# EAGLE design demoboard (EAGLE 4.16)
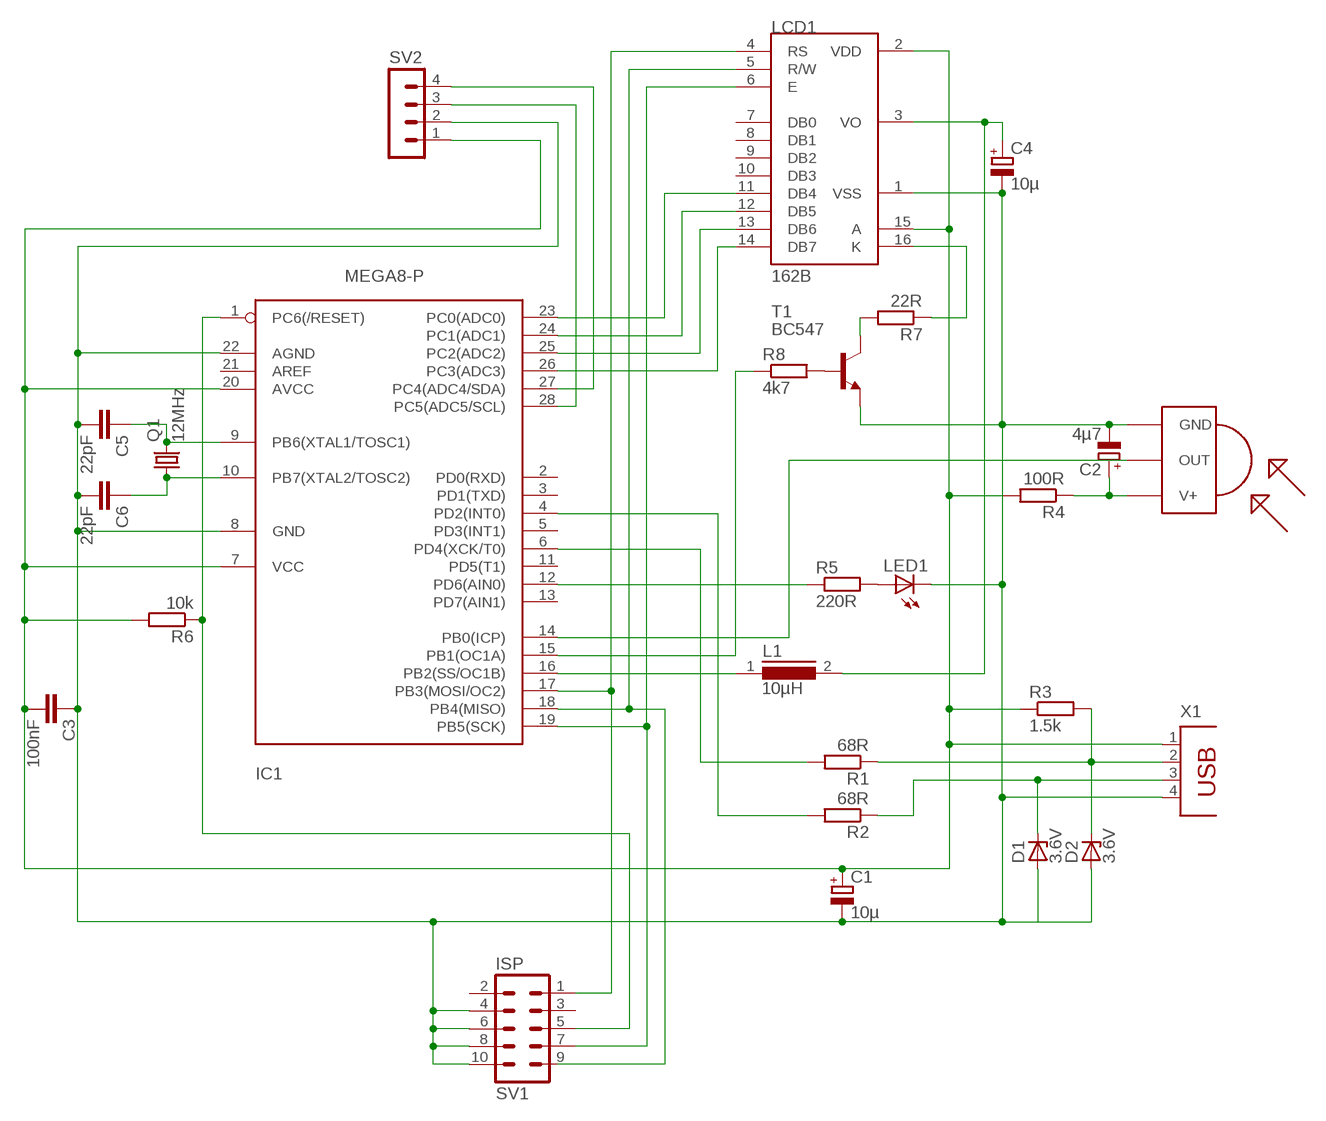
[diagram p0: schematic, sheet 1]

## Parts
C1  10µ  CPOL-EUE2.5-6  [E2,5-6]
C2  4µ7  CPOL-EUE2.5-6  [E2,5-6]
C3  100nF  C-EU025-025X050  [C025-025X050]
C4  10µ  CPOL-EUE2.5-6  [E2,5-6]
C5  22pF  C-EU025-025X050  [C025-025X050]
C6  22pF  C-EU025-025X050  [C025-025X050]
D1  3.6V  1N4728  [DO41Z10]
D2  3.6V  1N4728  [DO41Z10]
IC1  MEGA8-P  [DIL28-3]
L1  10µH  MICC10  [MICC10]
LCD1  162B  [162B]
LED1  LED3MM  [LED3MM]
Q1  12MHz  CRYSTALHC49S  [HC49/S]
R1  68R  R-EU_0309/10  [0309/10]
R2  68R  R-EU_0309/10  [0309/10]
R3  1.5k  R-EU_0309/10  [0309/10]
R4  100R  R-EU_0309/10  [0309/10]
R5  220R  R-EU_0309/10  [0309/10]
R6  10k  R-EU_0309/10  [0309/10]
R7  22R  R-EU_0309/10  [0309/10]
R8  4k7  R-EU_0309/10  [0309/10]
SV1  ISP  MA05-2  [MA05-2]
SV2  MA04-1  [MA04-1]
T1  BC547  [TO92]
TSOP1738  TSOP1738  [TSOP17XX]
X1  PN61729  [PN61729]

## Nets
N$1: IC1.4(PD2(INT0)) R2.2
N$2: IC1.6(PD4(XCK/T0)) R1.2
N$4: D1.C R2.1 X1.3
N$5: C5.1 IC1.9(PB6(XTAL1/TOSC1)) Q1.2
N$6: C6.1 IC1.10(PB7(XTAL2/TOSC2)) Q1.1
N$8: R7.2 T1.3(C)
N$9: IC1.14(PB0(ICP)) TSOP1738.OUT
N$10: C2.+ R4.1 TSOP1738.V+
N$11: LED1.A R5.2
N$12: IC1.12(PD6(AIN0)) R5.1
N$13: IC1.17(PB3(MOSI/OC2)) LCD1.4(RS) SV1.1
N$14: IC1.1(PC6(/RESET)) R6.1 SV1.5
N$15: IC1.19(PB5(SCK)) LCD1.6(E) SV1.7
N$16: IC1.18(PB4(MISO)) LCD1.5(R/W) SV1.9
N$17: IC1.23(PC0(ADC0)) LCD1.11(DB4)
N$18: IC1.24(PC1(ADC1)) LCD1.12(DB5)
N$19: IC1.25(PC2(ADC2)) LCD1.13(DB6)
N$20: D2.C R1.1 R3.2 X1.2
N$21: IC1.26(PC3(ADC3)) LCD1.14(DB7)
N$22: C1.+ C3.2 IC1.7(VCC) IC1.20(AVCC) LCD1.2(VDD) LCD1.15(A) R3.1 R4.2 R6.2 SV2.1 X1.1
N$23: R8.2 T1.2(B)
N$24: IC1.15(PB1(OC1A)) R8.1
N$25: LCD1.16(K) R7.1
N$27: IC1.16(PB2(SS/OC1B)) L1.1
N$28: C4.+ L1.2 LCD1.3(VO)
N$29: IC1.27(PC4(ADC4/SDA)) SV2.4
N$30: IC1.28(PC5(ADC5/SCL)) SV2.3
N$31: C1.- C2.- C3.1 C4.- C5.2 C6.2 D1.A D2.A IC1.8(GND) IC1.22(AGND) LCD1.1(VSS) LED1.K(C) SV1.4 SV1.6 SV1.8 SV1.10 SV2.2 T1.1(E) TSOP1738.GND X1.4
Unconnected: IC1.2(PD0(RXD)) IC1.3(PD1(TXD)) IC1.5(PD3(INT1)) IC1.11(PD5(T1)) IC1.13(PD7(AIN1)) IC1.21(AREF) LCD1.7(DB0) LCD1.8(DB1) LCD1.9(DB2) LCD1.10(DB3) SV1.2 SV1.3

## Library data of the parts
C1 C2 C4 = rcl:CPOL-EU: POLARIZED CAPACITOR, European symbol
C3 C5 C6 = rcl:C-EU: CAPACITOR, European symbol
D1 D2 = diode:1N4728: Z DIODE
IC1 = avr-1:MEGA8-P: MICROCONTROLLER 8 Kbytes FLASH 1 kbytes SRAM 512 bytes EEPROM USART 4-channel 10 bit ADC 2-channel 8 bit ADC
L1 = inductors:MICC10: INDUCTOR
LCD1 = peaktech:162B
LED1 = led:LED: LED
Q1 = crystal:CRYSTAL: CRYSTAL
R1-R8 = rcl:R-EU_: RESISTOR, European symbol
SV1 = con-lstb:MA05-2: PIN HEADER
SV2 = con-lstb:MA04-1: PIN HEADER
T1 = transistor-npn:BC547*: NPN Transistor
TSOP1738 = tsop:TSOP1738: IR Receiver and Demodulator
X1 = con-berg:PN61729: BERG USB connector

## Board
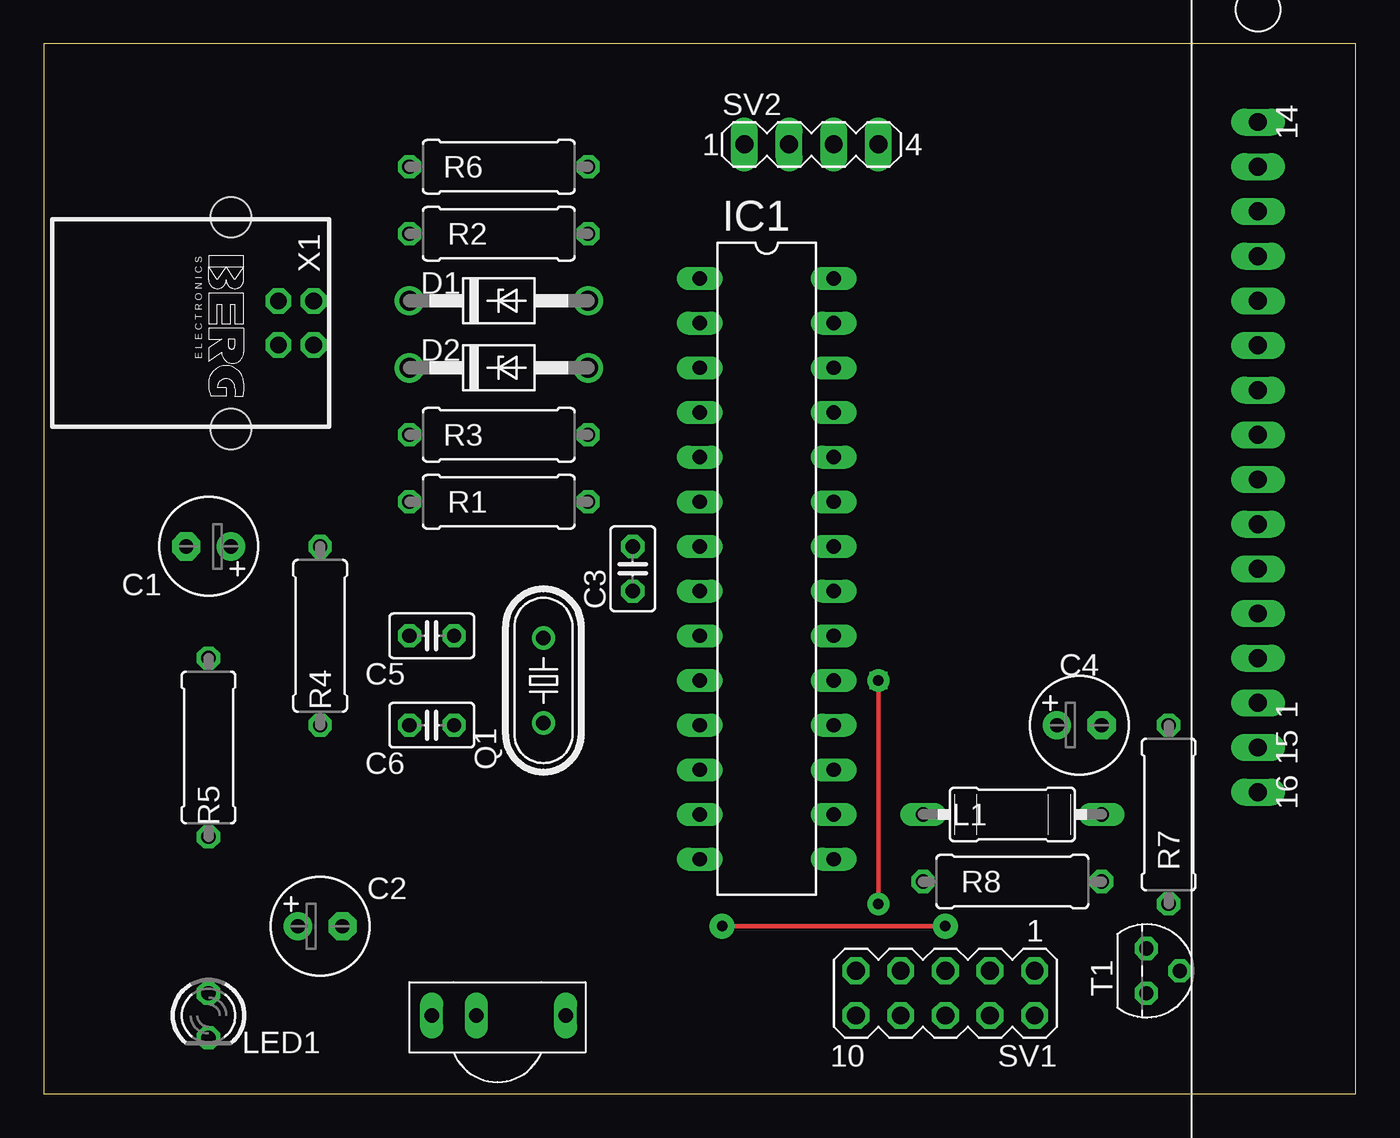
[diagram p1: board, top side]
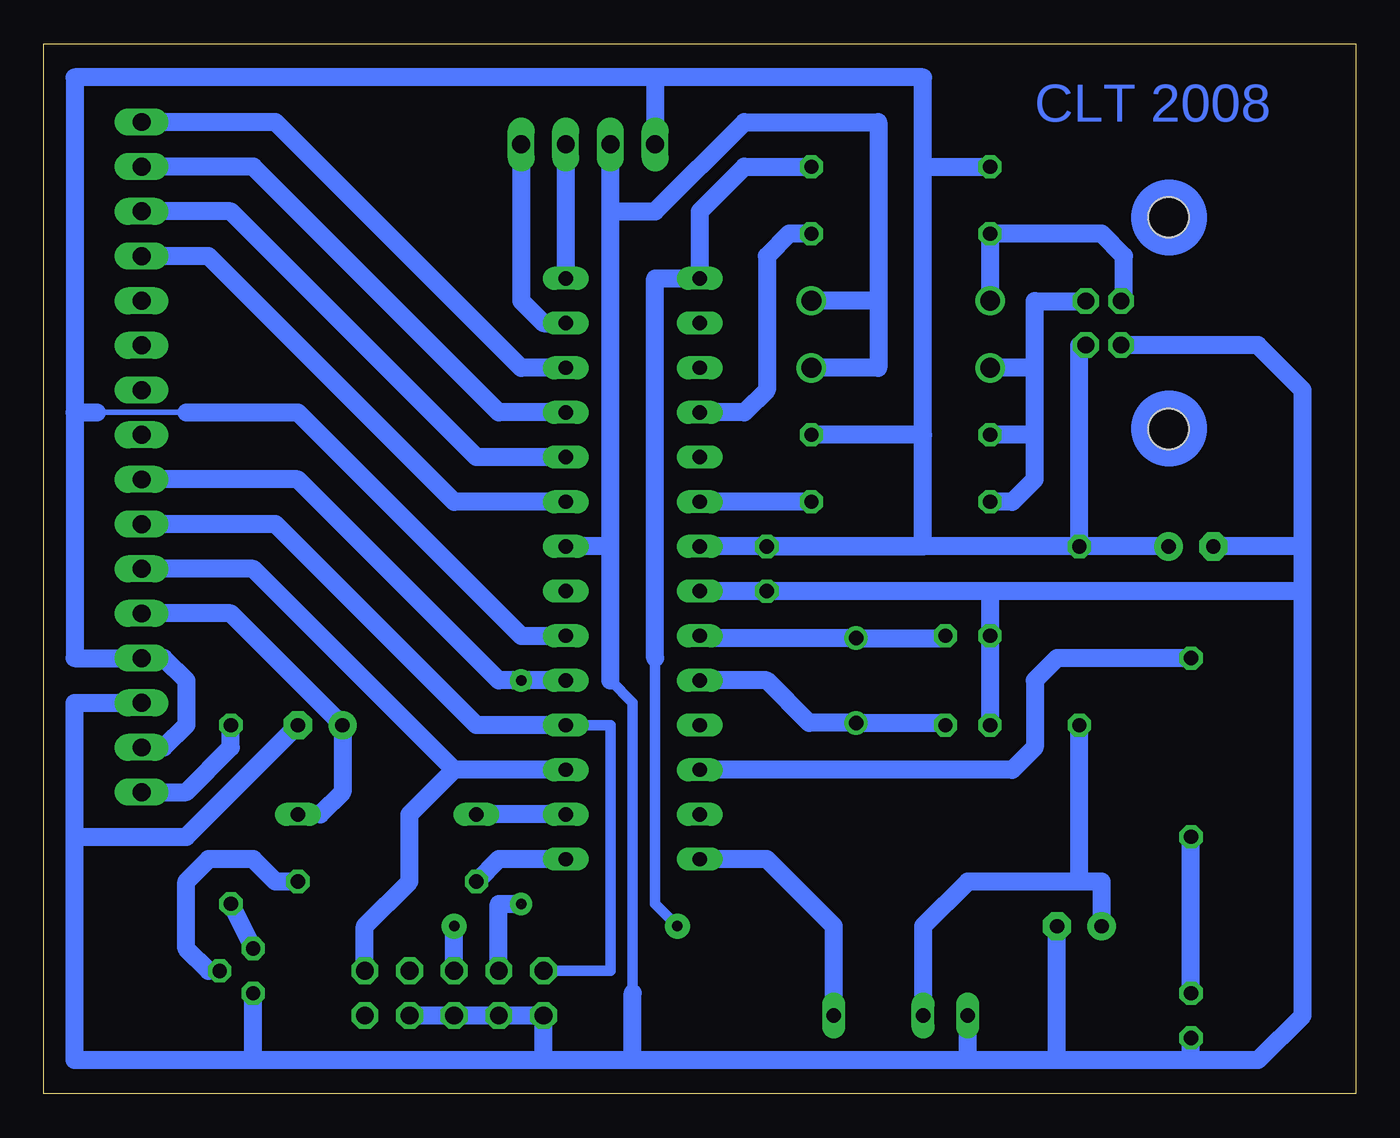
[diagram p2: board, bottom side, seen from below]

Size 74.6 x 59.68 mm. Coordinates in mm from the lower left corner, seen from the top.
Outline: 0,0 74.6,0 74.6,59.68 0,59.68 0,0
Copper layers (1*16): Top 0.035mm / dielectric 1.5mm / Bottom 0.035mm
Design rules "default": minimum track width 10mil, minimum drill 24mil, track to track 8mil, track to pad 8mil, pad to pad 8mil, via to via 8mil, smd to smd 8mil, copper to edge 40mil, drill to drill 8mil, minimum pad ring 10mil, minimum via ring 8mil, stop-mask expansion 4mil, vias tented up to drill 0mil, thermal gap 10mil

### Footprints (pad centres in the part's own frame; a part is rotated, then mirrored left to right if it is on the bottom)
E2,5-6 = drill 0.813 pad 1.6 round: + -1.27,0 | drill 0.813 pad 1.6 octagon: - 1.27,0
C025-025X050 = drill 0.813 octagon: 1 -1.27,0; 2 1.27,0
DO41Z10 = drill 1.118 round: A 5.08,0; C -5.08,0
DIL28-3 = drill 0.813 long: 1 -16.51,-3.81; 2 -13.97,-3.81; 3 -11.43,-3.81; 4 -8.89,-3.81; 5 -6.35,-3.81; 6 -3.81,-3.81; 7 -1.27,-3.81; 8 1.27,-3.81; 9 3.81,-3.81; 10 6.35,-3.81; 11 8.89,-3.81; 12 11.43,-3.81; 13 13.97,-3.81; 14 16.51,-3.81; 15 16.51,3.81; 16 13.97,3.81; 17 11.43,3.81; 18 8.89,3.81; 19 6.35,3.81; 20 3.81,3.81; 21 1.27,3.81; 22 -1.27,3.81; 23 -3.81,3.81; 24 -6.35,3.81; 25 -8.89,3.81; 26 -11.43,3.81; 27 -13.97,3.81; 28 -16.51,3.81
MICC10 = drill 0.813 long: 1 -5.08,0; 2 5.08,0
162B = drill 1.016 long: 1 33.02,0; 2 30.48,0; 3 27.94,0; 4 25.4,0; 5 22.86,0; 6 20.32,0; 7 17.78,0; 8 15.24,0; 9 12.7,0; 10 10.16,0; 11 7.62,0; 12 5.08,0; 13 2.54,0; 14 0,0; 15 35.56,0; 16 38.1,0
LED3MM = drill 0.813 octagon: A -1.27,0; K 1.27,0
HC49/S = drill 0.813 round: 1 -2.413,0; 2 2.413,0
0309/10 = drill 0.813 octagon: 1 -5.08,0; 2 5.08,0
MA05-2 = drill 1.016 octagon: 1 -5.08,-1.27; 2 -5.08,1.27; 3 -2.54,-1.27; 4 -2.54,1.27; 5 0,-1.27; 6 0,1.27; 7 2.54,-1.27; 8 2.54,1.27; 9 5.08,-1.27; 10 5.08,1.27
MA04-1 = drill 1.016 long: 1 -3.81,0; 2 -1.27,0; 3 1.27,0; 4 3.81,0
TO92 = drill 0.813 octagon: 1 1.27,0; 2 0,1.905; 3 -1.27,0
TSOP17XX = drill 0.813 long: GND -3.81,0; OUT 3.81,0; V+ -1.27,0
PN61729 = drill 0.95 octagon: 1 1.25,4.71; 2 -1.25,4.71; 3 -1.25,2.71; 4 1.25,2.71 | hole 2.3: -6.02,0; 6.02,0

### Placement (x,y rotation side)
C1  9.36,31.11 180 top
C2  15.71,9.52 0 top
C3  33.49,29.84 90 top
C4  58.89,20.95 0 top
C5  22.06,26.03 180 top
C6  22.06,20.95 180 top
D1  25.87,45.08 0 top
D2  25.87,41.27 0 top
IC1  41.11,29.84 270 top
L1  55.08,15.87 0 top
LCD1  69.05,55.24 270 top
LED1  9.36,4.44 270 top
Q1  28.41,23.49 90 top
R1  25.87,33.65 0 top
R2  25.87,48.89 0 top
R3  25.87,37.46 180 top
R4  15.71,26.03 90 top
R5  9.36,19.68 270 top
R6  25.87,52.7 180 top
R7  63.97,15.87 270 top
R8  55.08,12.06 0 top
SV1  51.27,5.71 180 top
SV2  43.65,53.97 0 top
T1  62.7,6.98 270 top
TSOP1738  25.87,4.44 0 top
X1  10.63,43.81 270 top

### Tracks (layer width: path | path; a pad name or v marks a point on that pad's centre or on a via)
N$1
  Bottom 1.016: R2.2 32.22,48.89 33.49,47.62 33.49,40 34.76,38.73 IC1.4
N$2
  Bottom 1.016: R1.2 IC1.6
N$4
  Bottom 0.406: 15.71,48.89 15.88,48.72
  Bottom 0.813: X1.3 13.17,45.06
  Bottom 1.016: 13.17,45.06 13.17,47.62 14.44,48.89 15.71,48.89 R2.1 D1.C
N$5
  Bottom 0.406: 37.3,25.9 IC1.9
  Bottom 1.016: 37.3,25.9 Q1.2 23.46,25.9 C5.1
N$6
  Bottom 1.016: IC1.10 33.49,23.49 31.08,21.08 Q1.1 23.46,21.08 C6.1
N$7  (via drill 0.6 pad 1.27)
  other vias: 47.46,10.79
N$8
  Bottom 1.016: R7.2 T1.3
N$9
  Bottom 1.016: IC1.14 33.49,13.33 29.68,9.52 TSOP1738.OUT
N$10
  Bottom 1.016: 15.71,12.06 R4.1 | 15.71,12.06 22.06,12.06 24.6,9.52 TSOP1738.V+ | C2.+ 14.44,12.06 15.71,12.06
N$11
  Bottom 1.016: LED1.A R5.2
N$12
  Bottom 1.016: IC1.12 19.52,18.41 18.25,19.68 18.25,23.49 16.98,24.76 R5.1
N$13
  Bottom 1.016: IC1.17 51.27,18.41 | SV1.1 56.35,9.52 53.81,12.06 53.81,15.87 51.27,18.41 | 51.27,18.41 62.7,29.84 LCD1.4
N$14  (via drill 0.6 pad 1.42)
  Top 0.254: v38.57,9.52 v51.27,9.52
  Bottom 0.61: v38.57,9.52 39.84,10.79 39.84,24.76
  Bottom 1.016: R6.1 34.76,52.7 37.3,50.16 IC1.1 39.84,46.35 39.84,24.76 | SV1.5 v51.27,9.52
N$15  (via drill 0.6)  (1 unrouted)
  Top 0.254: v47.46,23.49 47.46,10.79
  Bottom 1.016: IC1.19 v47.46,23.49 48.73,23.49 60.16,34.92 LCD1.6 | SV1.7 48.73,10.79 47.46,10.79
N$16
  Bottom 0.61: SV1.9 42.38,6.98 42.38,20.95 IC1.18
  Bottom 1.016: IC1.18 50,20.95 61.43,32.38 LCD1.5
N$17
  Bottom 1.016: IC1.23 51.27,33.65 65.24,47.62 LCD1.11
N$18
  Bottom 1.016: IC1.24 50,36.19 63.97,50.16 LCD1.12
N$19
  Bottom 1.016: IC1.25 48.73,38.73 62.7,52.7 LCD1.13
N$20
  Bottom 0.406: 18.25,45.08 18.23,45.06
  Bottom 1.016: 18.23,45.06 X1.2 | 18.25,37.46 18.25,34.92 19.52,33.65 R1.1 | 18.25,37.46 18.25,41.27 | 18.25,41.27 18.25,45.08 | 18.25,37.46 R3.2 | 18.25,41.27 D2.C
N$21
  Bottom 1.016: IC1.26 47.46,41.27 61.43,55.24 LCD1.14
N$22
  Bottom 0.305: 71.59,38.73 66.51,38.73
  Bottom 1.016: R4.2 24.6,31.11 | C3.2 24.6,31.11 | 24.6,31.11 IC1.7 | 24.6,52.7 R6.2 | 24.6,31.11 24.6,37.46 | 24.6,37.46 24.6,52.7 | 24.6,52.7 24.6,57.78 39.84,57.78 | 72.86,38.73 72.86,57.78 39.84,57.78 | 72.86,38.73 72.86,24.76 LCD1.2 67.78,24.76 66.51,23.49 66.51,20.95 67.78,19.68 LCD1.15 | X1.1 15.69,42.56 15.71,42.54 R4.2 | C1.+ R4.2 | 39.84,57.78 SV2.1 | IC1.20 47.46,26.03 60.16,38.73 66.51,38.73 | 72.86,38.73 71.59,38.73 | 24.6,37.46 R3.1
N$23
  Bottom 1.016: T1.2 65.24,6.98 66.51,8.25 66.51,12.06 65.24,13.33 62.7,13.33 61.43,12.06 R8.2
N$24
  Bottom 1.016: IC1.15 48.73,13.33 R8.1
N$25
  Bottom 1.016: LCD1.16 66.51,17.14 63.97,19.68 R7.1
N$26  (via drill 0.6 pad 1.27)
  other vias: 47.46,23.49
N$27
  Bottom 1.016: IC1.16 L1.1
N$28
  Bottom 1.016: LCD1.3 63.97,27.3 C4.+ 57.62,17.14 58.89,15.87 L1.2
N$29
  Bottom 1.016: SV2.4 47.46,45.08 46.19,43.81 IC1.27
N$30
  Bottom 1.016: SV2.3 IC1.28
N$31
  Bottom 0.406: 20.79,28.57 8.09,28.57
  Bottom 0.61: 42.38,23.49 41.11,22.22 41.11,5.71
  Bottom 1.016: 22.06,1.9 41.11,1.9 | 41.11,1.9 46.19,1.9 | SV1.4 SV1.6 SV1.8 SV1.10 46.19,1.9 | IC1.8 C3.1 20.79,28.57 | 16.98,1.9 C2.- | 16.98,1.9 22.06,1.9 | 9.36,1.9 16.98,1.9 | 9.36,1.9 LED1.K | 9.36,1.9 5.55,1.9 3.01,4.44 3.01,28.57 | 22.06,1.9 TSOP1738.GND | 3.01,28.57 20.79,28.57 | LCD1.1 72.86,22.22 72.86,14.6 | 72.86,14.6 72.86,1.9 62.7,1.9 | 46.19,1.9 62.7,1.9 | X1.4 5.55,42.56 5.55,42.54 3.01,40 3.01,31.11 | 3.01,28.57 3.01,31.11 | 3.01,31.11 C1.- | 62.7,1.9 T1.1 | 72.86,14.6 66.51,14.6 C4.- | C6.2 C5.2 20.79,28.57 | 42.38,23.49 42.38,31.11 | 42.38,31.11 42.38,50.16 | 42.38,50.16 SV2.2 | 42.38,31.11 IC1.22 | 41.11,1.9 41.11,5.71 | 27.14,45.08 27.14,55.24 34.76,55.24 39.84,50.16 42.38,50.16 | 27.14,45.08 27.14,41.27 D2.A | 27.14,45.08 D1.A
(copper drawn outside any net)
  shapes: Bottom circle x2

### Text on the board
Bottom: CLT 2008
